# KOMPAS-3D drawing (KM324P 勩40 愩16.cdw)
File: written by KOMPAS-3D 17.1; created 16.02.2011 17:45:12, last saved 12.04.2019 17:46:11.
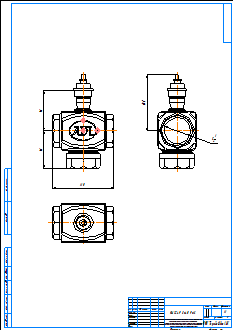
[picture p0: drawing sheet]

Title block, sheet 1: name: KM324P Ду40 Ру16; material: Внимание! Данный продукт является объектом авторского права ООО «Торговый Дом АДЛ». / Запрещается изменение, копирование, распространение / (в том числе путем копирования на другие сайты и ресурсы в Интернете) / или любое иное использование информации и объектов без предварительного / согласия правообладателя (ООО «Торговый Дом АДЛ»).; scale: 1:1; sheets: 1; organisation: ООО "Торговый дом АДЛ"; sheet format: A2; stored path: \\adlc.lan\data\АДЛ_ПКД\3D-модели\ADL production\Клапаны ГРАНРЕГ\Трёхходовой клапан KM324P\KOMPAS 2D\KM324P Ду40 Ру16.cdw

Views: Спереди 1, Проекционный вид 2, Проекционный вид 3
Dimensions and other numbers on the sheet: 110; 72; 68; 101; 1:1; 1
